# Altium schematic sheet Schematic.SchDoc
size A; SheetNumber: 2; SheetTotal: 2
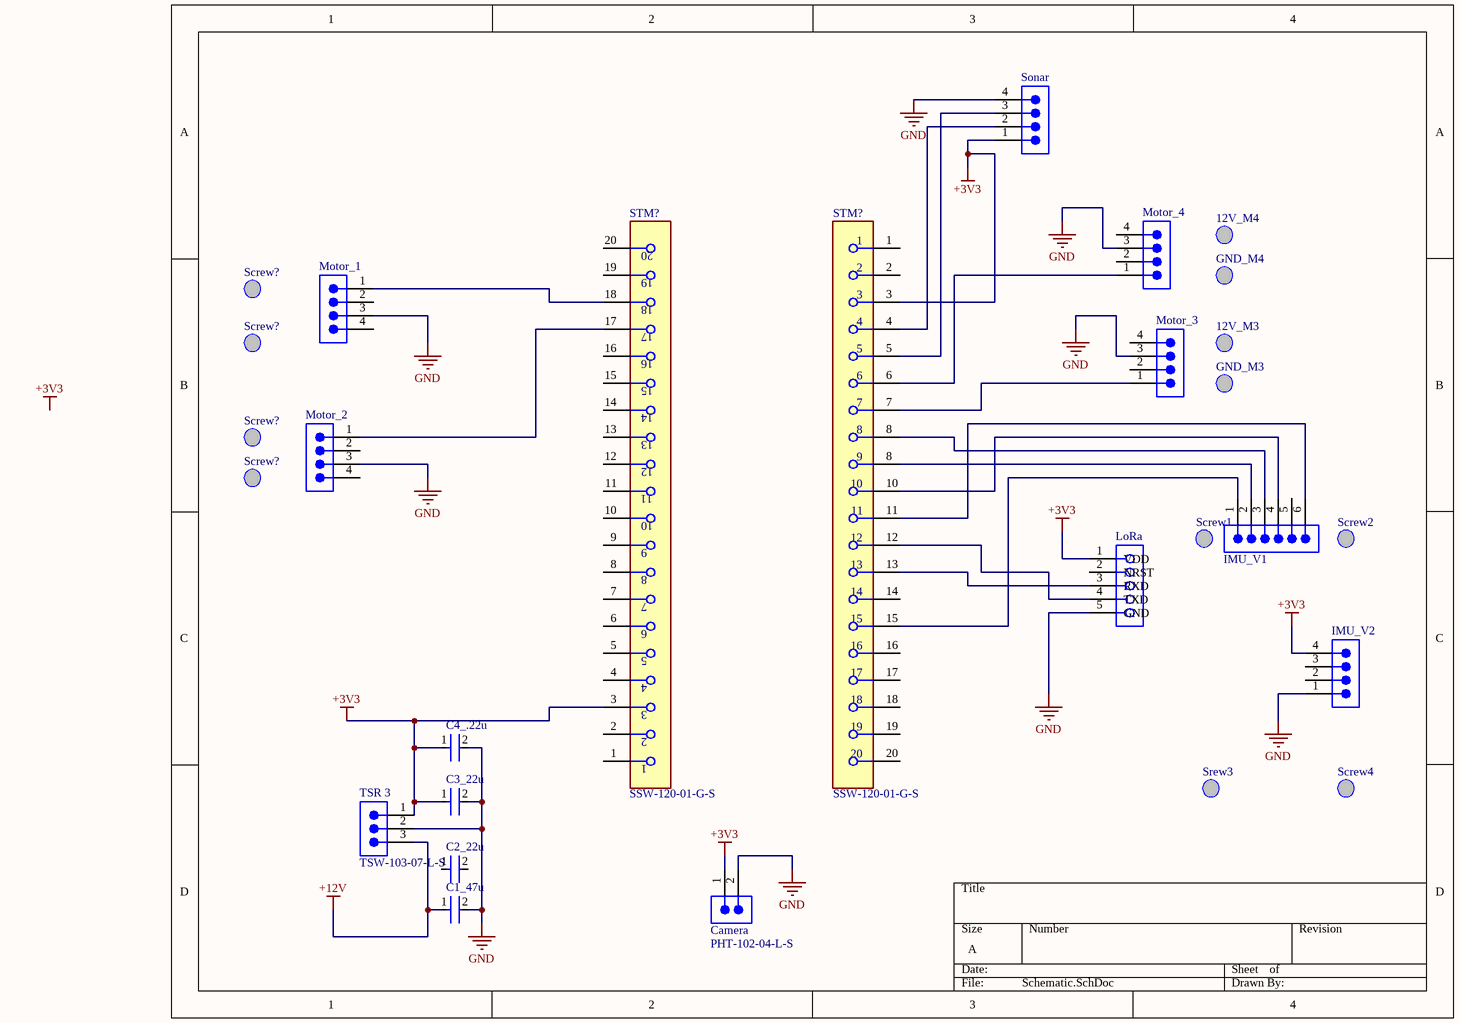
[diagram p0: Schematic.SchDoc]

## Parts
(Parts that share a designator on the sheet are numbered #1, #2 ... from top to bottom, then left to right.)
12V_M3  MountingHoles_3.2mm  (value not drawn)
12V_M4  MountingHoles_3.2mm  (value not drawn)
C1_47u  C3216X5R1E476M160AC  [FP-C3216-160-0_2-MFG]  (value not drawn)
C2_22u  C1206C224K5RACTU  [FP-C1206C-EB-MFG]  (value not drawn)
C3_22u  C1206C224K5RACTU  [FP-C1206C-EB-MFG]  (value not drawn)
C4_.22u  12065C224JAT2A  [FP-1206-L_3_2_0_2-W_1_6_0-IPC_C]  (value not drawn)
Camera  PHT-102-04-L-S  [SMTC-PHT-102-04-X-S]
GND_M3  MountingHoles_3.2mm  (value not drawn)
GND_M4  MountingHoles_3.2mm  (value not drawn)
IMU_V1  PHT-106-01-L-S  [SMTC-PHT-106-01-X-S]  (value not drawn)
IMU_V2  TSW-104-08-F-S  [SMTC-TSW-104-08-X-S]  (value not drawn)
LoRa  SSW-105-01-G-S  [SMTC-SSW-105-01-X-S]  (value not drawn)
Motor_1  TSW-104-08-F-S  [SMTC-TSW-104-08-X-S]  (value not drawn)
Motor_2  TSW-104-08-F-S  [SMTC-TSW-104-08-X-S]  (value not drawn)
Motor_3  TSW-104-08-F-S  [SMTC-TSW-104-08-X-S]  (value not drawn)
Motor_4  TSW-104-08-F-S  [SMTC-TSW-104-08-X-S]  (value not drawn)
Screw1  MountingHoles_3.2mm  (value not drawn)
Screw2  MountingHoles_3.2mm  (value not drawn)
Screw4  MountingHoles_3.2mm  (value not drawn)
Screw?#1  MountingHoles_3.2mm  (value not drawn)
Screw?#2  MountingHoles_3.2mm  (value not drawn)
Screw?#3  MountingHoles_3.2mm  (value not drawn)
Screw?#4  MountingHoles_3.2mm  (value not drawn)
Sonar  TSW-104-08-F-S  [SMTC-TSW-104-08-X-S]  (value not drawn)
Srew3  MountingHoles_3.2mm  (value not drawn)
STM?#1  SSW-120-01-G-S  [FP-SSW-120-01-G-S-MFG]
STM?#2  SSW-120-01-G-S  [FP-SSW-120-01-G-S-MFG]
TSR_3  TSW-103-07-L-S  [SMTC-TSW-103-07-X-S]

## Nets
+3V3: C3_22u.1 C4_.22u.1 Camera.1 IMU_V2.4 LoRa.1(VDD) Sonar.1 STM?#1.3(3V3) STM?#2.3(5V) TSR_3.1
+12V: C1_47u.1 TSR_3.3
GND: C1_47u.2 C3_22u.2 C4_.22u.2 Camera.2 IMU_V2.1 LoRa.5(GND) Motor_1.3 Motor_2.3 Motor_3.3 Motor_4.3 Sonar.4 TSR_3.2
NetIMU_V1_1: IMU_V1.1 STM?#1.15(A0)
NetIMU_V1_2: IMU_V1.2 STM?#1.8(A6)
NetIMU_V1_3: IMU_V1.3 STM?#1.8(A7)
NetIMU_V1_4: IMU_V1.4 STM?#1.10(A5)
NetIMU_V1_6: IMU_V1.6 STM?#1.11(A4)
NetLoRa_3: LoRa.3(RXD) STM?#1.13(A2)
NetLoRa_4: LoRa.4(TXD) STM?#1.12(A3)
NetMotor_1_1: Motor_1.1 STM?#2.18(B14)
NetMotor_2_1: Motor_2.1 STM?#2.17(B15)
NetMotor_3_1: Motor_3.1 STM?#1.7(B0)
NetMotor_4_1: Motor_4.1 STM?#1.6(B1)
NetSonar_2: Sonar.2 STM?#1.4(B10)
NetSonar_3: Sonar.3 STM?#1.5(B2)

Not connected (* = marked no-connect by the designer): C2_22u 1 2; IMU_V1 5; IMU_V2 2 3; LoRa 2(NRST); Motor_1 2 4; Motor_2 2 4; Motor_3 2 4; Motor_4 2 4; STM?#1 1(5V) 2(GND) 14(A1) 16(NRST) 17(C15) 18(C14) 19(C13) 20(VBAT); STM?#2 1(3V3) 2(GND) 4(B9) 5(B8) 6(B7) 7(B6) 8(B5) 9(B4) 10(B3) 11(A15) 12(A12) 13(A11) 14(A10) 15(A9) 16(A8) 19(B13) 20(B12)

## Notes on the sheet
- Labels drawn without touching a wire or pin: +3V3

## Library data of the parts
C1_47u = CMP-2000-05397-3: Multilayer Ceramic Capacitors 47uF ±20% 25V X5R SMD 1206
C2_22u C3_22u = CMP-03020-014280-1: CAP CER 0.22UF 50V X7R 1206; Manufacturer: KEMET; Value: 0.22 μF; Description: C1206 0.22 μF X7R 10.00% 50 V; Automotive Grade: Grade 0; Tolerance: 0.1; Material: Ceramic; Temperature Coefficient: 15%
C4_.22u = CMP-04427-007236-1: General Purpose Ceramic Capacitor, 1206, 220nF, 5%, X7R, 15%, 50V
Camera = CMP-1024-00181-1: Press Fit Header, Through-hole, Vertical, -55 to 125 degC, 2.54 mm Pitch, 2-Pin, Male, RoHS; Manufacturer: Samtec; Pitch: 2.54 mm
IMU_V1 = CMP-1024-00187-1: Press Fit Header, Through-hole, Vertical, -55 to 125 degC, 2.54 mm Pitch, 6-Pin, Male, RoHS; Manufacturer: Samtec; Pitch: 2.54 mm
IMU_V2 Motor_1-Motor_4 Sonar = CMP-1024-00355-1: 0.025" SQ Post Header, Through-hole, Vertical, -55 to 125 degC, 2.54 mm Pitch, 4-Pin, Male, RoHS; Manufacturer: Samtec; Pitch: 2.54 mm
LoRa = CMP-1023-00344-1: SQ Post Socket, Through-hole, Vertical, -55 to 125 degC, 2.54mm Pitch, 5-Pin, Female, RoHS; Manufacturer: Samtec
STM?#1 STM?#2 = CMP-00575-00296075-1: SSW-120-01-G-S SSW - Samtec 2.54mm Single Row Straight Socket Strip 8.5 Profile (mcv)(TO22); NexarPartId: 296075; Manufacturer Lifecycle Status: PRODUCTION; Number of Contacts: 20; Gender: Receptacle; Connector Type: Receptacle, Socket; Contact Resistance: 10mΩ; Voltage Rating: 550V; Voltage Rating (DC): 655V; Voltage Rating (AC): 465V; Current Rating: 6.9A; Lead Length: 2.64mm
TSR_3 = CMP-1024-00334-1: 0.025" SQ Post Header, Through-hole, Vertical, -55 to 125 degC, 2.54 mm Pitch, 3-Pin, Male, RoHS; Manufacturer: Samtec; Pitch: 2.54 mm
